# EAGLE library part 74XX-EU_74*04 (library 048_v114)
Hex INVERTER
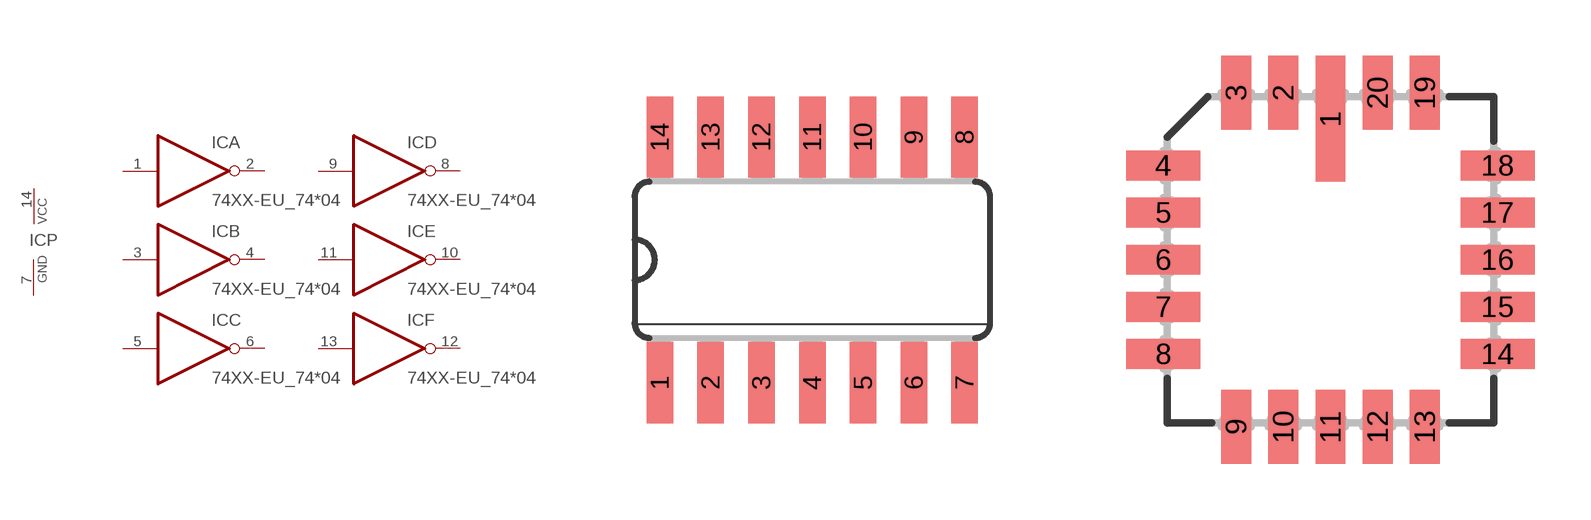
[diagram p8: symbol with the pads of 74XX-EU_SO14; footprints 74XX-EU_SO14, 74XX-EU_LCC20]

Designator prefix IC; gates A=74XX-EU_7404 B=74XX-EU_7404 C=74XX-EU_7404 D=74XX-EU_7404 E=74XX-EU_7404 F=74XX-EU_7404 P=74XX-EU_PWRN

## 74XX-EU_7404D, 74XX-EU_74AC04D, 74XX-EU_74ACT04D, 74XX-EU_74ALS04D, 74XX-EU_74AS04D, 74XX-EU_74HC04D, 74XX-EU_74HCT04D, 74XX-EU_74LS04D, 74XX-EU_74S04D  [74XX-EU_SO14]
1  A:I  in
2  A:O  out
3  B:I  in
4  B:O  out
5  C:I  in
6  C:O  out
7  P:GND  pwr
8  D:O  out
9  D:I  in
10  E:O  out
11  E:I  in
12  F:O  out
13  F:I  in
14  P:VCC  pwr

## 74XX-EU_7404FK, 74XX-EU_74AC04FK, 74XX-EU_74ACT04FK, 74XX-EU_74HC04FK, 74XX-EU_74HCT04FK, 74XX-EU_74LS04FK, 74XX-EU_74S04FK  [74XX-EU_LCC20]
2  A:I  in
3  A:O  out
4  B:I  in
6  B:O  out
8  C:I  in
9  C:O  out
10  P:GND  pwr
12  D:O  out
13  D:I  in
14  E:O  out
16  E:I  in
18  F:O  out
19  F:I  in
20  P:VCC  pwr

## 74XX-EU_7404N, 74XX-EU_74AC04N, 74XX-EU_74ACT04N, 74XX-EU_74ALS04N, 74XX-EU_74AS04N, 74XX-EU_74HC04N, 74XX-EU_74HCT04N, 74XX-EU_74LS04N, 74XX-EU_74S04N  [74XX-EU_DIL14]
Pads as for 74XX-EU_SO14

## Footprint 74XX-EU_SO14 (pad centres in mm)
Small Outline package 150 mil
smd 0.66 x 2.032: 1 -3.81,-3.073; 2 -2.54,-3.073; 3 -1.27,-3.073; 4 0,-3.073; 5 1.27,-3.073; 6 2.54,-3.073; 7 3.81,-3.073; 8 3.81,3.073; 9 2.54,3.073; 10 1.27,3.073; 11 0,3.073; 12 -1.27,3.073; 13 -2.54,3.073; 14 -3.81,3.073

## Footprint 74XX-EU_LCC20 (pad centres in mm)
Leadless Chip Carrier Ceramic Package
smd 0.8 x 3.4: 1 0,3.8
smd 0.8 x 2: 2 -1.27,4.5; 3 -2.54,4.5; 9 -2.54,-4.5; 10 -1.27,-4.5; 11 0,-4.5; 12 1.27,-4.5; 13 2.54,-4.5; 19 2.54,4.5; 20 1.27,4.5
smd 2 x 0.8: 4 -4.5,2.54; 5 -4.5,1.27; 6 -4.5,0; 7 -4.5,-1.27; 8 -4.5,-2.54; 14 4.5,-2.54; 15 4.5,-1.27; 16 4.5,0; 17 4.5,1.27; 18 4.5,2.54

## Footprint 74XX-EU_DIL14 (pad centres in mm)
Dual In Line Package
drill 0.813 long: 1 -7.62,-3.81; 2 -5.08,-3.81; 3 -2.54,-3.81; 4 0,-3.81; 5 2.54,-3.81; 6 5.08,-3.81; 7 7.62,-3.81; 8 7.62,3.81; 9 5.08,3.81; 10 2.54,3.81; 11 0,3.81; 12 -2.54,3.81; 13 -5.08,3.81; 14 -7.62,3.81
